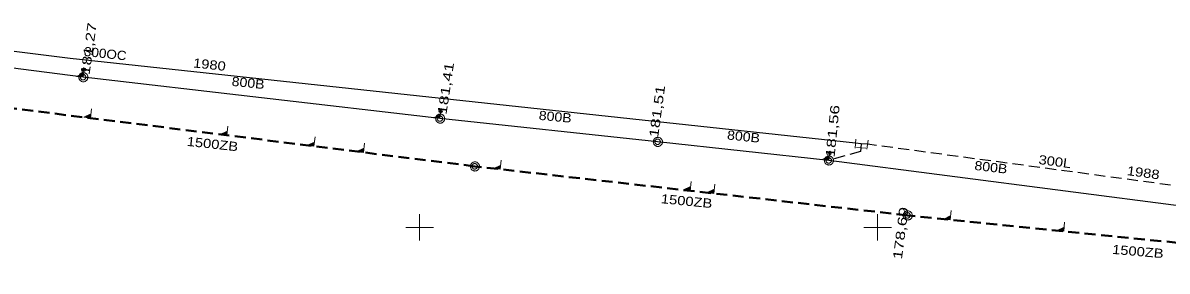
# Model space of a CAD drawing. Extents: x -740851 to -738888, y -1041382 to -1040235.
# Drawn here: x -740143.3 to -740018.4, y -1040454.8 to -1040427.7 of the extents above; entities that cross this region are included whole.
import ezdxf

# ---------------------------------------------------------------- set-up
doc = ezdxf.new("R2010")
doc.units = 0
doc.header["$LTSCALE"] = 0.4
doc.linetypes.add('MEDIUM_DASHED', pattern=[4.5, 3, -1.5])
for name, color, linetype, lineweight in [('1', 7, 'Continuous', 13), ('18', 7, 'Continuous', 13), ('8', 7, 'Continuous', 13)]:
    doc.layers.add(name, color=color, linetype=linetype, lineweight=lineweight)

msp = doc.modelspace()

# ---------------------------------------------------------------- linework, layer by layer
at = {"layer": '1'}
for p, q in [((-740100, -1040448.571), (-740100, -1040451.429)), ((-740050, -1040448.571), (-740050, -1040451.429)), ((-740101.48, -1040450), (-740098.48, -1040450)), ((-740051.48, -1040450), (-740048.48, -1040450))]:
    msp.add_line(p, q, dxfattribs=at)
at = {"layer": '18', "lineweight": 25}
for p, q in [((-740136.73, -1040433.63), (-740175.27, -1040428.77)), ((-740097.77, -1040438.14), (-740136.73, -1040433.63)), ((-740074, -1040440.67), (-740097.77, -1040438.14)), ((-740055.32, -1040442.7), (-740074, -1040440.67)), ((-740016.53, -1040447.73), (-740055.32, -1040442.7))]:
    msp.add_line(p, q, dxfattribs=at)
at = {"layer": '18', "linetype": 'MEDIUM_DASHED', "lineweight": 40}
for p, q in [((-740093.97, -1040443.35), (-740151.51, -1040436.14)), ((-740046.72, -1040448.69), (-740093.97, -1040443.35)), ((-739986.78, -1040454.76), (-740046.72, -1040448.69))]:
    msp.add_line(p, q, dxfattribs=at)
at = {"layer": '18'}
for points in [[(-740136.612, -1040432.63), (-740136.727, -1040433.628), (-740137.439, -1040433.545), (-740136.675, -1040433.178)], [(-740136.739, -1040433.272), (-740136.773, -1040433.562), (-740137.228, -1040433.51), (-740136.734, -1040433.272)], [(-740136.804, -1040433.371), (-740136.821, -1040433.516), (-740137.054, -1040433.489), (-740136.799, -1040433.371)], [(-740135.809, -1040437.089), (-740135.934, -1040438.089), (-740136.647, -1040438), (-740135.877, -1040437.638)], [(-740135.942, -1040437.732), (-740135.979, -1040438.023), (-740136.435, -1040437.966), (-740135.938, -1040437.732)], [(-740136.008, -1040437.83), (-740136.026, -1040437.976), (-740136.26, -1040437.947), (-740136.003, -1040437.831)], [(-740097.661, -1040437.14), (-740097.767, -1040438.138), (-740098.479, -1040438.062), (-740097.719, -1040437.688)], [(-740097.782, -1040437.782), (-740097.813, -1040438.073), (-740098.268, -1040438.024), (-740097.778, -1040437.783)], [(-740097.846, -1040437.881), (-740097.862, -1040438.027), (-740098.095, -1040438.002), (-740097.841, -1040437.882)], [(-740120.925, -1040438.954), (-740121.05, -1040439.954), (-740121.764, -1040439.865), (-740120.994, -1040439.503)], [(-740121.059, -1040439.597), (-740121.095, -1040439.888), (-740121.551, -1040439.831), (-740121.054, -1040439.597)], [(-740121.124, -1040439.695), (-740121.143, -1040439.841), (-740121.377, -1040439.812), (-740121.12, -1040439.696)], [(-740111.399, -1040440.148), (-740111.525, -1040441.148), (-740112.238, -1040441.058), (-740111.468, -1040440.697)], [(-740111.533, -1040440.79), (-740111.57, -1040441.082), (-740112.026, -1040441.025), (-740111.529, -1040440.791)], [(-740111.599, -1040440.889), (-740111.617, -1040441.035), (-740111.851, -1040441.005), (-740111.594, -1040440.89)], [(-740105.992, -1040440.826), (-740106.117, -1040441.826), (-740106.831, -1040441.736), (-740106.061, -1040441.374)], [(-740106.126, -1040441.468), (-740106.162, -1040441.759), (-740106.618, -1040441.702), (-740106.121, -1040441.469)], [(-740106.191, -1040441.567), (-740106.21, -1040441.712), (-740106.443, -1040441.683), (-740106.187, -1040441.567)], [(-740091.067, -1040442.663), (-740091.18, -1040443.663), (-740091.894, -1040443.582), (-740091.129, -1040443.212)], [(-740055.189, -1040441.707), (-740055.317, -1040442.698), (-740056.025, -1040442.606), (-740055.259, -1040442.251)], [(-740055.324, -1040442.343), (-740055.362, -1040442.632), (-740055.814, -1040442.573), (-740055.32, -1040442.344)], [(-740055.39, -1040442.441), (-740055.409, -1040442.585), (-740055.64, -1040442.555), (-740055.385, -1040442.441)], [(-740091.193, -1040443.306), (-740091.226, -1040443.597), (-740091.682, -1040443.546), (-740091.188, -1040443.307)], [(-740091.257, -1040443.405), (-740091.274, -1040443.551), (-740091.507, -1040443.524), (-740091.252, -1040443.406)], [(-740070.349, -1040445.004), (-740070.462, -1040446.004), (-740071.175, -1040445.924), (-740070.411, -1040445.553)], [(-740067.765, -1040445.296), (-740067.878, -1040446.296), (-740068.592, -1040446.216), (-740067.827, -1040445.845)], [(-740070.475, -1040445.648), (-740070.508, -1040445.939), (-740070.963, -1040445.887), (-740070.47, -1040445.648)], [(-740070.539, -1040445.747), (-740070.556, -1040445.892), (-740070.789, -1040445.866), (-740070.534, -1040445.747)], [(-740067.891, -1040445.94), (-740067.924, -1040446.231), (-740068.38, -1040446.179), (-740067.886, -1040445.94)], [(-740067.955, -1040446.039), (-740067.972, -1040446.184), (-740068.206, -1040446.158), (-740067.951, -1040446.039)], [(-740041.945, -1040448.161), (-740042.046, -1040449.161), (-740042.76, -1040449.089), (-740042, -1040448.71)], [(-740042.063, -1040448.805), (-740042.093, -1040449.096), (-740042.548, -1040449.05), (-740042.058, -1040448.805)], [(-740042.126, -1040448.904), (-740042.141, -1040449.05), (-740042.375, -1040449.026), (-740042.121, -1040448.905)], [(-740029.558, -1040449.415), (-740029.659, -1040450.415), (-740030.373, -1040450.343), (-740029.614, -1040449.964)], [(-740029.676, -1040450.059), (-740029.706, -1040450.35), (-740030.162, -1040450.304), (-740029.672, -1040450.06)], [(-740029.74, -1040450.159), (-740029.754, -1040450.304), (-740029.988, -1040450.281), (-740029.735, -1040450.159)]]:
    msp.add_lwpolyline(points, dxfattribs=at)
for points in [[(-740136.2, -1040433.64), (-740136.21, -1040433.59), (-740136.21, -1040433.54), (-740136.23, -1040433.49), (-740136.25, -1040433.44), (-740136.27, -1040433.39), (-740136.3, -1040433.35), (-740136.33, -1040433.31), (-740136.37, -1040433.27), (-740136.41, -1040433.24), (-740136.45, -1040433.21), (-740136.5, -1040433.19), (-740136.55, -1040433.17), (-740136.6, -1040433.15), (-740136.65, -1040433.15), (-740136.7, -1040433.14), (-740136.75, -1040433.15), (-740136.8, -1040433.15), (-740136.85, -1040433.17), (-740136.9, -1040433.19), (-740136.95, -1040433.21), (-740136.99, -1040433.24), (-740137.03, -1040433.27), (-740137.07, -1040433.31), (-740137.1, -1040433.35), (-740137.13, -1040433.39), (-740137.15, -1040433.44), (-740137.17, -1040433.49), (-740137.19, -1040433.54), (-740137.19, -1040433.59), (-740137.2, -1040433.64), (-740137.19, -1040433.69), (-740137.19, -1040433.74), (-740137.17, -1040433.79), (-740137.15, -1040433.84), (-740137.13, -1040433.89), (-740137.1, -1040433.93), (-740137.07, -1040433.97), (-740137.03, -1040434.01), (-740136.99, -1040434.04), (-740136.95, -1040434.07), (-740136.9, -1040434.09), (-740136.85, -1040434.11), (-740136.8, -1040434.13), (-740136.75, -1040434.13), (-740136.7, -1040434.14), (-740136.65, -1040434.13), (-740136.6, -1040434.13), (-740136.55, -1040434.11), (-740136.5, -1040434.09), (-740136.45, -1040434.07), (-740136.41, -1040434.04), (-740136.37, -1040434.01), (-740136.33, -1040433.97), (-740136.3, -1040433.93), (-740136.27, -1040433.89), (-740136.25, -1040433.84), (-740136.23, -1040433.79), (-740136.21, -1040433.74), (-740136.21, -1040433.69)], [(-740136.43, -1040433.63), (-740136.43, -1040433.6), (-740136.436, -1040433.57), (-740136.442, -1040433.54), (-740136.454, -1040433.51), (-740136.472, -1040433.48), (-740136.49, -1040433.456), (-740136.508, -1040433.432), (-740136.532, -1040433.408), (-740136.556, -1040433.39), (-740136.58, -1040433.372), (-740136.61, -1040433.354), (-740136.64, -1040433.342), (-740136.67, -1040433.336), (-740136.7, -1040433.33), (-740136.73, -1040433.33), (-740136.76, -1040433.33), (-740136.79, -1040433.336), (-740136.82, -1040433.342), (-740136.85, -1040433.354), (-740136.88, -1040433.372), (-740136.904, -1040433.39), (-740136.928, -1040433.408), (-740136.952, -1040433.432), (-740136.97, -1040433.456), (-740136.988, -1040433.48), (-740137.006, -1040433.51), (-740137.018, -1040433.54), (-740137.024, -1040433.57), (-740137.03, -1040433.6), (-740137.03, -1040433.63), (-740137.03, -1040433.66), (-740137.024, -1040433.69), (-740137.018, -1040433.72), (-740137.006, -1040433.75), (-740136.988, -1040433.78), (-740136.97, -1040433.804), (-740136.952, -1040433.828), (-740136.928, -1040433.852), (-740136.904, -1040433.87), (-740136.88, -1040433.888), (-740136.85, -1040433.906), (-740136.82, -1040433.918), (-740136.79, -1040433.924), (-740136.76, -1040433.93), (-740136.73, -1040433.93), (-740136.7, -1040433.93), (-740136.67, -1040433.924), (-740136.64, -1040433.918), (-740136.61, -1040433.906), (-740136.58, -1040433.888), (-740136.556, -1040433.87), (-740136.532, -1040433.852), (-740136.508, -1040433.828), (-740136.49, -1040433.804), (-740136.472, -1040433.78), (-740136.454, -1040433.75), (-740136.442, -1040433.72), (-740136.436, -1040433.69), (-740136.43, -1040433.66)], [(-740097.24, -1040438.15), (-740097.25, -1040438.1), (-740097.25, -1040438.05), (-740097.27, -1040438), (-740097.29, -1040437.95), (-740097.31, -1040437.9), (-740097.34, -1040437.86), (-740097.37, -1040437.82), (-740097.41, -1040437.78), (-740097.45, -1040437.75), (-740097.49, -1040437.72), (-740097.54, -1040437.7), (-740097.59, -1040437.68), (-740097.64, -1040437.66), (-740097.69, -1040437.66), (-740097.74, -1040437.65), (-740097.79, -1040437.66), (-740097.84, -1040437.66), (-740097.89, -1040437.68), (-740097.94, -1040437.7), (-740097.99, -1040437.72), (-740098.03, -1040437.75), (-740098.07, -1040437.78), (-740098.11, -1040437.82), (-740098.14, -1040437.86), (-740098.17, -1040437.9), (-740098.19, -1040437.95), (-740098.21, -1040438), (-740098.23, -1040438.05), (-740098.23, -1040438.1), (-740098.24, -1040438.15), (-740098.23, -1040438.2), (-740098.23, -1040438.25), (-740098.21, -1040438.3), (-740098.19, -1040438.35), (-740098.17, -1040438.4), (-740098.14, -1040438.44), (-740098.11, -1040438.48), (-740098.07, -1040438.52), (-740098.03, -1040438.55), (-740097.99, -1040438.58), (-740097.94, -1040438.6), (-740097.89, -1040438.62), (-740097.84, -1040438.64), (-740097.79, -1040438.64), (-740097.74, -1040438.65), (-740097.69, -1040438.64), (-740097.64, -1040438.64), (-740097.59, -1040438.62), (-740097.54, -1040438.6), (-740097.49, -1040438.58), (-740097.45, -1040438.55), (-740097.41, -1040438.52), (-740097.37, -1040438.48), (-740097.34, -1040438.44), (-740097.31, -1040438.4), (-740097.29, -1040438.35), (-740097.27, -1040438.3), (-740097.25, -1040438.25), (-740097.25, -1040438.2)], [(-740097.47, -1040438.14), (-740097.47, -1040438.11), (-740097.476, -1040438.08), (-740097.482, -1040438.05), (-740097.494, -1040438.02), (-740097.512, -1040437.99), (-740097.53, -1040437.966), (-740097.548, -1040437.942), (-740097.572, -1040437.918), (-740097.596, -1040437.9), (-740097.62, -1040437.882), (-740097.65, -1040437.864), (-740097.68, -1040437.852), (-740097.71, -1040437.846), (-740097.74, -1040437.84), (-740097.77, -1040437.84), (-740097.8, -1040437.84), (-740097.83, -1040437.846), (-740097.86, -1040437.852), (-740097.89, -1040437.864), (-740097.92, -1040437.882), (-740097.944, -1040437.9), (-740097.968, -1040437.918), (-740097.992, -1040437.942), (-740098.01, -1040437.966), (-740098.028, -1040437.99), (-740098.046, -1040438.02), (-740098.058, -1040438.05), (-740098.064, -1040438.08), (-740098.07, -1040438.11), (-740098.07, -1040438.14), (-740098.07, -1040438.17), (-740098.064, -1040438.2), (-740098.058, -1040438.23), (-740098.046, -1040438.26), (-740098.028, -1040438.29), (-740098.01, -1040438.314), (-740097.992, -1040438.338), (-740097.968, -1040438.362), (-740097.944, -1040438.38), (-740097.92, -1040438.398), (-740097.89, -1040438.416), (-740097.86, -1040438.428), (-740097.83, -1040438.434), (-740097.8, -1040438.44), (-740097.77, -1040438.44), (-740097.74, -1040438.44), (-740097.71, -1040438.434), (-740097.68, -1040438.428), (-740097.65, -1040438.416), (-740097.62, -1040438.398), (-740097.596, -1040438.38), (-740097.572, -1040438.362), (-740097.548, -1040438.338), (-740097.53, -1040438.314), (-740097.512, -1040438.29), (-740097.494, -1040438.26), (-740097.482, -1040438.23), (-740097.476, -1040438.2), (-740097.47, -1040438.17)], [(-740073.47, -1040440.68), (-740073.48, -1040440.63), (-740073.48, -1040440.58), (-740073.5, -1040440.53), (-740073.52, -1040440.48), (-740073.54, -1040440.43), (-740073.57, -1040440.39), (-740073.6, -1040440.35), (-740073.64, -1040440.31), (-740073.68, -1040440.28), (-740073.72, -1040440.25), (-740073.77, -1040440.23), (-740073.82, -1040440.21), (-740073.87, -1040440.19), (-740073.92, -1040440.19), (-740073.97, -1040440.18), (-740074.02, -1040440.19), (-740074.07, -1040440.19), (-740074.12, -1040440.21), (-740074.17, -1040440.23), (-740074.22, -1040440.25), (-740074.26, -1040440.28), (-740074.3, -1040440.31), (-740074.34, -1040440.35), (-740074.37, -1040440.39), (-740074.4, -1040440.43), (-740074.42, -1040440.48), (-740074.44, -1040440.53), (-740074.46, -1040440.58), (-740074.46, -1040440.63), (-740074.47, -1040440.68), (-740074.46, -1040440.73), (-740074.46, -1040440.78), (-740074.44, -1040440.83), (-740074.42, -1040440.88), (-740074.4, -1040440.93), (-740074.37, -1040440.97), (-740074.34, -1040441.01), (-740074.3, -1040441.05), (-740074.26, -1040441.08), (-740074.22, -1040441.11), (-740074.17, -1040441.13), (-740074.12, -1040441.15), (-740074.07, -1040441.17), (-740074.02, -1040441.17), (-740073.97, -1040441.18), (-740073.92, -1040441.17), (-740073.87, -1040441.17), (-740073.82, -1040441.15), (-740073.77, -1040441.13), (-740073.72, -1040441.11), (-740073.68, -1040441.08), (-740073.64, -1040441.05), (-740073.6, -1040441.01), (-740073.57, -1040440.97), (-740073.54, -1040440.93), (-740073.52, -1040440.88), (-740073.5, -1040440.83), (-740073.48, -1040440.78), (-740073.48, -1040440.73)], [(-740073.7, -1040440.67), (-740073.7, -1040440.64), (-740073.706, -1040440.61), (-740073.712, -1040440.58), (-740073.724, -1040440.55), (-740073.742, -1040440.52), (-740073.76, -1040440.496), (-740073.778, -1040440.472), (-740073.802, -1040440.448), (-740073.826, -1040440.43), (-740073.85, -1040440.412), (-740073.88, -1040440.394), (-740073.91, -1040440.382), (-740073.94, -1040440.376), (-740073.97, -1040440.37), (-740074, -1040440.37), (-740074.03, -1040440.37), (-740074.06, -1040440.376), (-740074.09, -1040440.382), (-740074.12, -1040440.394), (-740074.15, -1040440.412), (-740074.174, -1040440.43), (-740074.198, -1040440.448), (-740074.222, -1040440.472), (-740074.24, -1040440.496), (-740074.258, -1040440.52), (-740074.276, -1040440.55), (-740074.288, -1040440.58), (-740074.294, -1040440.61), (-740074.3, -1040440.64), (-740074.3, -1040440.67), (-740074.3, -1040440.7), (-740074.294, -1040440.73), (-740074.288, -1040440.76), (-740074.276, -1040440.79), (-740074.258, -1040440.82), (-740074.24, -1040440.844), (-740074.222, -1040440.868), (-740074.198, -1040440.892), (-740074.174, -1040440.91), (-740074.15, -1040440.928), (-740074.12, -1040440.946), (-740074.09, -1040440.958), (-740074.06, -1040440.964), (-740074.03, -1040440.97), (-740074, -1040440.97), (-740073.97, -1040440.97), (-740073.94, -1040440.964), (-740073.91, -1040440.958), (-740073.88, -1040440.946), (-740073.85, -1040440.928), (-740073.826, -1040440.91), (-740073.802, -1040440.892), (-740073.778, -1040440.868), (-740073.76, -1040440.844), (-740073.742, -1040440.82), (-740073.724, -1040440.79), (-740073.712, -1040440.76), (-740073.706, -1040440.73), (-740073.7, -1040440.7)], [(-740093.44, -1040443.36), (-740093.45, -1040443.31), (-740093.45, -1040443.26), (-740093.47, -1040443.21), (-740093.49, -1040443.16), (-740093.51, -1040443.11), (-740093.54, -1040443.07), (-740093.57, -1040443.03), (-740093.61, -1040442.99), (-740093.65, -1040442.96), (-740093.69, -1040442.93), (-740093.74, -1040442.91), (-740093.79, -1040442.89), (-740093.84, -1040442.87), (-740093.89, -1040442.87), (-740093.94, -1040442.86), (-740093.99, -1040442.87), (-740094.04, -1040442.87), (-740094.09, -1040442.89), (-740094.14, -1040442.91), (-740094.19, -1040442.93), (-740094.23, -1040442.96), (-740094.27, -1040442.99), (-740094.31, -1040443.03), (-740094.34, -1040443.07), (-740094.37, -1040443.11), (-740094.39, -1040443.16), (-740094.41, -1040443.21), (-740094.43, -1040443.26), (-740094.43, -1040443.31), (-740094.44, -1040443.36), (-740094.43, -1040443.41), (-740094.43, -1040443.46), (-740094.41, -1040443.51), (-740094.39, -1040443.56), (-740094.37, -1040443.61), (-740094.34, -1040443.65), (-740094.31, -1040443.69), (-740094.27, -1040443.73), (-740094.23, -1040443.76), (-740094.19, -1040443.79), (-740094.14, -1040443.81), (-740094.09, -1040443.83), (-740094.04, -1040443.85), (-740093.99, -1040443.85), (-740093.94, -1040443.86), (-740093.89, -1040443.85), (-740093.84, -1040443.85), (-740093.79, -1040443.83), (-740093.74, -1040443.81), (-740093.69, -1040443.79), (-740093.65, -1040443.76), (-740093.61, -1040443.73), (-740093.57, -1040443.69), (-740093.54, -1040443.65), (-740093.51, -1040443.61), (-740093.49, -1040443.56), (-740093.47, -1040443.51), (-740093.45, -1040443.46), (-740093.45, -1040443.41)], [(-740054.79, -1040442.71), (-740054.8, -1040442.66), (-740054.8, -1040442.61), (-740054.82, -1040442.56), (-740054.84, -1040442.51), (-740054.86, -1040442.46), (-740054.89, -1040442.42), (-740054.92, -1040442.38), (-740054.96, -1040442.34), (-740055, -1040442.31), (-740055.04, -1040442.28), (-740055.09, -1040442.26), (-740055.14, -1040442.24), (-740055.19, -1040442.22), (-740055.24, -1040442.22), (-740055.29, -1040442.21), (-740055.34, -1040442.22), (-740055.39, -1040442.22), (-740055.44, -1040442.24), (-740055.49, -1040442.26), (-740055.54, -1040442.28), (-740055.58, -1040442.31), (-740055.62, -1040442.34), (-740055.66, -1040442.38), (-740055.69, -1040442.42), (-740055.72, -1040442.46), (-740055.74, -1040442.51), (-740055.76, -1040442.56), (-740055.78, -1040442.61), (-740055.78, -1040442.66), (-740055.79, -1040442.71), (-740055.78, -1040442.76), (-740055.78, -1040442.81), (-740055.76, -1040442.86), (-740055.74, -1040442.91), (-740055.72, -1040442.96), (-740055.69, -1040443), (-740055.66, -1040443.04), (-740055.62, -1040443.08), (-740055.58, -1040443.11), (-740055.54, -1040443.14), (-740055.49, -1040443.16), (-740055.44, -1040443.18), (-740055.39, -1040443.2), (-740055.34, -1040443.2), (-740055.29, -1040443.21), (-740055.24, -1040443.2), (-740055.19, -1040443.2), (-740055.14, -1040443.18), (-740055.09, -1040443.16), (-740055.04, -1040443.14), (-740055, -1040443.11), (-740054.96, -1040443.08), (-740054.92, -1040443.04), (-740054.89, -1040443), (-740054.86, -1040442.96), (-740054.84, -1040442.91), (-740054.82, -1040442.86), (-740054.8, -1040442.81), (-740054.8, -1040442.76)], [(-740055.02, -1040442.7), (-740055.02, -1040442.67), (-740055.026, -1040442.64), (-740055.032, -1040442.61), (-740055.044, -1040442.58), (-740055.062, -1040442.55), (-740055.08, -1040442.526), (-740055.098, -1040442.502), (-740055.122, -1040442.478), (-740055.146, -1040442.46), (-740055.17, -1040442.442), (-740055.2, -1040442.424), (-740055.23, -1040442.412), (-740055.26, -1040442.406), (-740055.29, -1040442.4), (-740055.32, -1040442.4), (-740055.35, -1040442.4), (-740055.38, -1040442.406), (-740055.41, -1040442.412), (-740055.44, -1040442.424), (-740055.47, -1040442.442), (-740055.494, -1040442.46), (-740055.518, -1040442.478), (-740055.542, -1040442.502), (-740055.56, -1040442.526), (-740055.578, -1040442.55), (-740055.596, -1040442.58), (-740055.608, -1040442.61), (-740055.614, -1040442.64), (-740055.62, -1040442.67), (-740055.62, -1040442.7), (-740055.62, -1040442.73), (-740055.614, -1040442.76), (-740055.608, -1040442.79), (-740055.596, -1040442.82), (-740055.578, -1040442.85), (-740055.56, -1040442.874), (-740055.542, -1040442.898), (-740055.518, -1040442.922), (-740055.494, -1040442.94), (-740055.47, -1040442.958), (-740055.44, -1040442.976), (-740055.41, -1040442.988), (-740055.38, -1040442.994), (-740055.35, -1040443), (-740055.32, -1040443), (-740055.29, -1040443), (-740055.26, -1040442.994), (-740055.23, -1040442.988), (-740055.2, -1040442.976), (-740055.17, -1040442.958), (-740055.146, -1040442.94), (-740055.122, -1040442.922), (-740055.098, -1040442.898), (-740055.08, -1040442.874), (-740055.062, -1040442.85), (-740055.044, -1040442.82), (-740055.032, -1040442.79), (-740055.026, -1040442.76), (-740055.02, -1040442.73)], [(-740093.67, -1040443.35), (-740093.67, -1040443.32), (-740093.676, -1040443.29), (-740093.682, -1040443.26), (-740093.694, -1040443.23), (-740093.712, -1040443.2), (-740093.73, -1040443.176), (-740093.748, -1040443.152), (-740093.772, -1040443.128), (-740093.796, -1040443.11), (-740093.82, -1040443.092), (-740093.85, -1040443.074), (-740093.88, -1040443.062), (-740093.91, -1040443.056), (-740093.94, -1040443.05), (-740093.97, -1040443.05), (-740094, -1040443.05), (-740094.03, -1040443.056), (-740094.06, -1040443.062), (-740094.09, -1040443.074), (-740094.12, -1040443.092), (-740094.144, -1040443.11), (-740094.168, -1040443.128), (-740094.192, -1040443.152), (-740094.21, -1040443.176), (-740094.228, -1040443.2), (-740094.246, -1040443.23), (-740094.258, -1040443.26), (-740094.264, -1040443.29), (-740094.27, -1040443.32), (-740094.27, -1040443.35), (-740094.27, -1040443.38), (-740094.264, -1040443.41), (-740094.258, -1040443.44), (-740094.246, -1040443.47), (-740094.228, -1040443.5), (-740094.21, -1040443.524), (-740094.192, -1040443.548), (-740094.168, -1040443.572), (-740094.144, -1040443.59), (-740094.12, -1040443.608), (-740094.09, -1040443.626), (-740094.06, -1040443.638), (-740094.03, -1040443.644), (-740094, -1040443.65), (-740093.97, -1040443.65), (-740093.94, -1040443.65), (-740093.91, -1040443.644), (-740093.88, -1040443.638), (-740093.85, -1040443.626), (-740093.82, -1040443.608), (-740093.796, -1040443.59), (-740093.772, -1040443.572), (-740093.748, -1040443.548), (-740093.73, -1040443.524), (-740093.712, -1040443.5), (-740093.694, -1040443.47), (-740093.682, -1040443.44), (-740093.676, -1040443.41), (-740093.67, -1040443.38)], [(-740046.19, -1040448.7), (-740046.2, -1040448.65), (-740046.2, -1040448.6), (-740046.22, -1040448.55), (-740046.24, -1040448.5), (-740046.26, -1040448.45), (-740046.29, -1040448.41), (-740046.32, -1040448.37), (-740046.36, -1040448.33), (-740046.4, -1040448.3), (-740046.44, -1040448.27), (-740046.49, -1040448.25), (-740046.54, -1040448.23), (-740046.59, -1040448.21), (-740046.64, -1040448.21), (-740046.69, -1040448.2), (-740046.74, -1040448.21), (-740046.79, -1040448.21), (-740046.84, -1040448.23), (-740046.89, -1040448.25), (-740046.94, -1040448.27), (-740046.98, -1040448.3), (-740047.02, -1040448.33), (-740047.06, -1040448.37), (-740047.09, -1040448.41), (-740047.12, -1040448.45), (-740047.14, -1040448.5), (-740047.16, -1040448.55), (-740047.18, -1040448.6), (-740047.18, -1040448.65), (-740047.19, -1040448.7), (-740047.18, -1040448.75), (-740047.18, -1040448.8), (-740047.16, -1040448.85), (-740047.14, -1040448.9), (-740047.12, -1040448.95), (-740047.09, -1040448.99), (-740047.06, -1040449.03), (-740047.02, -1040449.07), (-740046.98, -1040449.1), (-740046.94, -1040449.13), (-740046.89, -1040449.15), (-740046.84, -1040449.17), (-740046.79, -1040449.19), (-740046.74, -1040449.19), (-740046.69, -1040449.2), (-740046.64, -1040449.19), (-740046.59, -1040449.19), (-740046.54, -1040449.17), (-740046.49, -1040449.15), (-740046.44, -1040449.13), (-740046.4, -1040449.1), (-740046.36, -1040449.07), (-740046.32, -1040449.03), (-740046.29, -1040448.99), (-740046.26, -1040448.95), (-740046.24, -1040448.9), (-740046.22, -1040448.85), (-740046.2, -1040448.8), (-740046.2, -1040448.75)], [(-740046.42, -1040448.69), (-740046.42, -1040448.66), (-740046.426, -1040448.63), (-740046.432, -1040448.6), (-740046.444, -1040448.57), (-740046.462, -1040448.54), (-740046.48, -1040448.516), (-740046.498, -1040448.492), (-740046.522, -1040448.468), (-740046.546, -1040448.45), (-740046.57, -1040448.432), (-740046.6, -1040448.414), (-740046.63, -1040448.402), (-740046.66, -1040448.396), (-740046.69, -1040448.39), (-740046.72, -1040448.39), (-740046.75, -1040448.39), (-740046.78, -1040448.396), (-740046.81, -1040448.402), (-740046.84, -1040448.414), (-740046.87, -1040448.432), (-740046.894, -1040448.45), (-740046.918, -1040448.468), (-740046.942, -1040448.492), (-740046.96, -1040448.516), (-740046.978, -1040448.54), (-740046.996, -1040448.57), (-740047.008, -1040448.6), (-740047.014, -1040448.63), (-740047.02, -1040448.66), (-740047.02, -1040448.69), (-740047.02, -1040448.72), (-740047.014, -1040448.75), (-740047.008, -1040448.78), (-740046.996, -1040448.81), (-740046.978, -1040448.84), (-740046.96, -1040448.864), (-740046.942, -1040448.888), (-740046.918, -1040448.912), (-740046.894, -1040448.93), (-740046.87, -1040448.948), (-740046.84, -1040448.966), (-740046.81, -1040448.978), (-740046.78, -1040448.984), (-740046.75, -1040448.99), (-740046.72, -1040448.99), (-740046.69, -1040448.99), (-740046.66, -1040448.984), (-740046.63, -1040448.978), (-740046.6, -1040448.966), (-740046.57, -1040448.948), (-740046.546, -1040448.93), (-740046.522, -1040448.912), (-740046.498, -1040448.888), (-740046.48, -1040448.864), (-740046.462, -1040448.84), (-740046.444, -1040448.81), (-740046.432, -1040448.78), (-740046.426, -1040448.75), (-740046.42, -1040448.72)]]:
    msp.add_lwpolyline(points, close=True, dxfattribs=at)
for centre, radius in [((-740136.634, -1040432.814), 0.189), ((-740136.635, -1040432.812), 0.0935), ((-740097.681, -1040437.324), 0.189), ((-740097.682, -1040437.322), 0.0934), ((-740055.213, -1040441.889), 0.188), ((-740055.214, -1040441.887), 0.093)]:
    msp.add_circle(centre, radius, dxfattribs=at)
at = {"layer": '8'}
for p, q in [((-740052.445, -1040441.37), (-740052.361, -1040440.37)), ((-740051.27, -1040441.373), (-740052.27, -1040441.293)), ((-740051.162, -1040441.48), (-740051.028, -1040440.48))]:
    msp.add_line(p, q, dxfattribs=at)
at = {"layer": '8', "lineweight": 25}
msp.add_line((-740051.772, -1040440.883), (-740051.81, -1040441.33), dxfattribs=at)
for points in [[(-740052.4, -1040440.83), (-740138.15, -1040431.58), (-740166.074, -1040428.12)], [(-740051.09, -1040440.94), (-740051.772, -1040440.883), (-740052.4, -1040440.83)]]:
    msp.add_lwpolyline(points, dxfattribs=at)
at = {"layer": '8', "linetype": 'MEDIUM_DASHED', "lineweight": 25}
for points in [[(-740051.81, -1040441.33), (-740051.842, -1040441.728), (-740055.32, -1040442.7)], [(-739963.421, -1040452.173), (-740012.64, -1040446.12), (-740051.09, -1040440.94)]]:
    msp.add_lwpolyline(points, dxfattribs=at)

# ---------------------------------------------------------------- texts
at = {"layer": '18'}
for s, rotation, width, p in [('181,27', 81.846, 1.4, (-740136.036, -1040433.439)), ('181,41', 81.536, 1.4, (-740097.061, -1040437.758)), ('800B', 354.318, 1.15, (-740120.541, -1040434.572)), ('181,51', 82.175, 1.4, (-740073.948, -1040440.26)), ('800B', 354.724, 1.15, (-740087.008, -1040438.271)), ('181,56', 84.266, 1.4, (-740054.684, -1040442.408)), ('1500ZB', 353.858, 1.2, (-740125.445, -1040441.111)), ('800B', 354.12, 1.15, (-740066.451, -1040440.41)), ('800B', 353.318, 1.15, (-740039.449, -1040443.731)), ('1500ZB', 354.552, 1.2, (-740073.673, -1040447.363)), ('178,69', 82.654, 1.4, (-740047.332, -1040453.533)), ('1500ZB', 355.218, 1.2, (-740024.402, -1040452.884))]:
    msp.add_text(s, height=1, rotation=rotation, dxfattribs=dict(at, width=width)).set_placement(p)
at = {"layer": '8'}
for s, rotation, width, p in [('300OC', 353.843, 1.1, (-740136.672, -1040431.307)), ('1980', 353.843, 1.2, (-740124.758, -1040432.565)), ('300L', 352.327, 1.2, (-740032.453, -1040443.083)), ('1988', 352.327, 1.2, (-740022.806, -1040444.296))]:
    msp.add_text(s, height=1, rotation=rotation, dxfattribs=dict(at, width=width)).set_placement(p)

doc.saveas('drawing.dxf')
